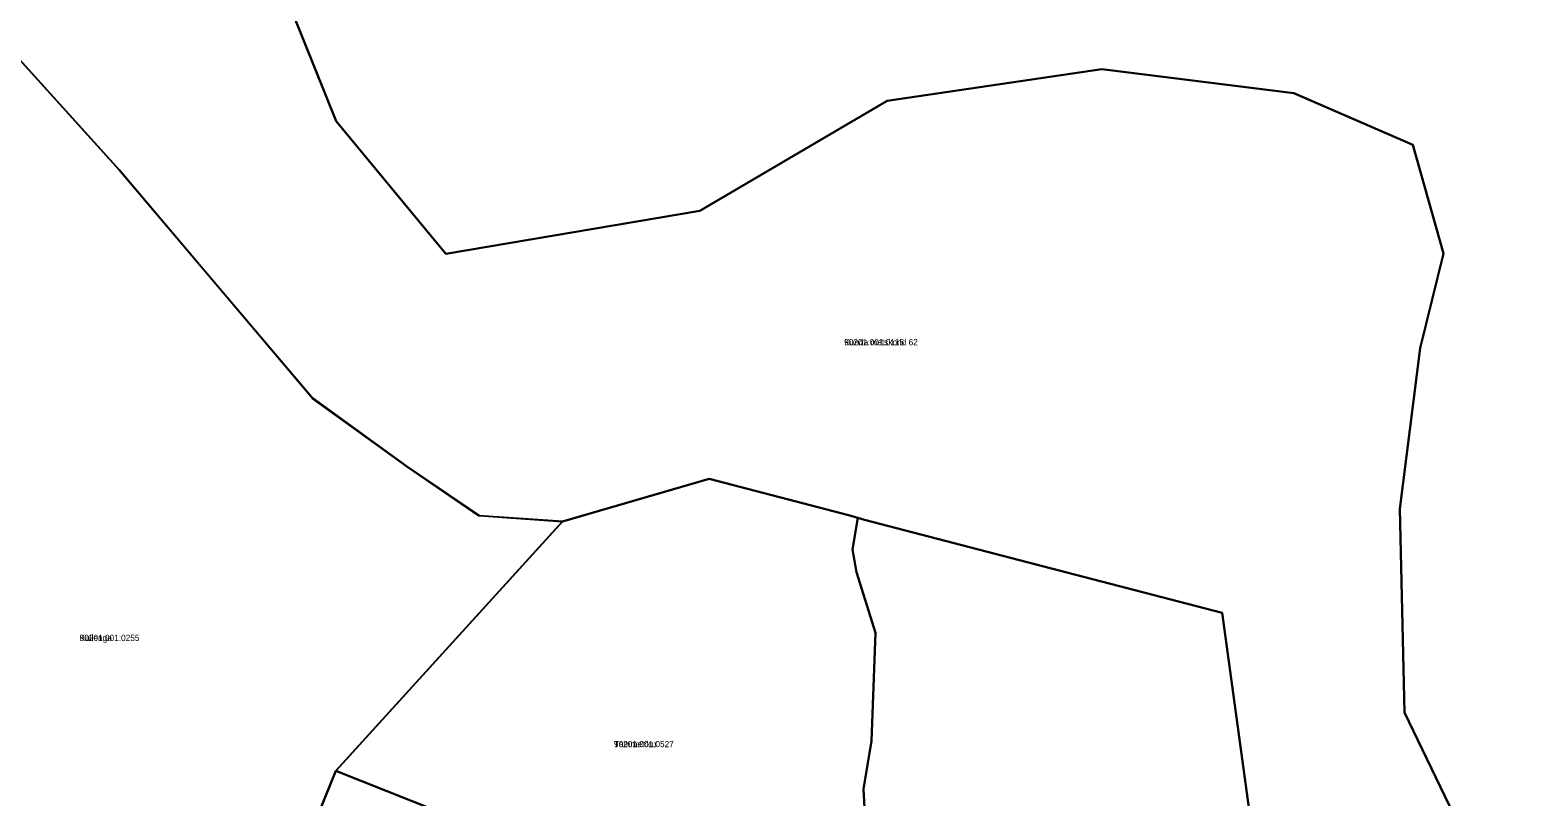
# Model space of a CAD drawing. Extents: x 634518 to 667988, y 6584667 to 6604739.
# Drawn here: x 639044.6 to 639410, y 6599120.4 to 6599306.3 of the extents above; entities that cross this region are included whole.
import ezdxf

# ---------------------------------------------------------------- set-up
doc = ezdxf.new("R2010")
doc.units = 0
for name, color, linetype in [('L_AADRESS', 7, 'Continuous'), ('PIIR', 7, 'Continuous'), ('TUNNUS', 7, 'Continuous')]:
    doc.layers.add(name, color=color, linetype=linetype)

msp = doc.modelspace()

# ---------------------------------------------------------------- linework, layer by layer
at = {"layer": 'PIIR'}
for points in [[(639100.56, 6599329.51), (639118.72, 6599284.25), (639145.3, 6599252.04), (639206.86, 6599262.51), (639252.25, 6599289.18), (639304.28, 6599296.85), (639350.81, 6599291.05), (639379.7, 6599278.52), (639387.08, 6599252.18), (639381.42, 6599229.17), (639376.55, 6599190.19), (639377.67, 6599140.79), (639393.99, 6599106.97), (639433.76, 6599069.98)], [(639433.76, 6599069.98), (639393.99, 6599106.97), (639377.67, 6599140.79), (639376.55, 6599190.19), (639381.42, 6599229.17), (639387.08, 6599252.18), (639379.7, 6599278.52), (639350.81, 6599291.05), (639304.28, 6599296.85), (639252.25, 6599289.18), (639206.86, 6599262.51), (639145.3, 6599252.04), (639118.72, 6599284.25), (639100.56, 6599329.51)], [(639441.3, 6598996.4), (639404.07, 6599015.97), (639378.12, 6599039.05), (639355.62, 6599071.96), (639341.87, 6599103.62), (639333.44, 6599165.02), (639297.96, 6599174.25), (639246.74, 6599187.59), (639245.19, 6599188.04), (639243.23, 6599188.58), (639209.09, 6599197.48), (639173.59, 6599187.14), (639153.27, 6599188.56), (639136.08, 6599200.34), (639113.01, 6599217.01), (639066.11, 6599272.45), (639036.47, 6599305.14), (638997.65, 6599321.26)]]:
    msp.add_lwpolyline(points, dxfattribs=at)
for points in [[(638939.52, 6598922.84), (638956.22, 6599045.86), (638963.81, 6599131.43), (639036.47, 6599305.14), (639066.16, 6599272.46), (639113.06, 6599217.03), (639136.09, 6599200.35), (639153.39, 6599188.58), (639173.59, 6599187.14), (639118.65, 6599126.67), (639114.82, 6599117.34), (639093.64, 6599086.65), (639078.76, 6599065.25), (639063.55, 6599043.7), (639051.11, 6599025.24), (639040.95, 6598997.58), (639033.5, 6598975.34), (639064.36, 6598966.67), (639057.8, 6598941.11), (639047.63, 6598901.35)], [(639143.03, 6599116.99), (639118.65, 6599126.67), (639173.59, 6599187.14), (639209.09, 6599197.48), (639243.23, 6599188.58), (639245.19, 6599188.04), (639243.83, 6599180.32), (639244.87, 6599174.9), (639249.45, 6599160.16), (639248.51, 6599133.96), (639246.5, 6599122.2), (639247.04, 6599113.24), (639245.63, 6599106.61), (639243.91, 6599100), (639242.74, 6599096.83), (639238.97, 6599090.63), (639222.06, 6599067.35), (639220.59, 6599068.27)], [(639295.43, 6599007.23), (639223.67, 6599066.34), (639222.06, 6599067.35), (639238.97, 6599090.63), (639242.74, 6599096.83), (639243.91, 6599100), (639245.63, 6599106.61), (639247.04, 6599113.24), (639246.5, 6599122.2), (639248.51, 6599133.96), (639249.45, 6599160.16), (639244.87, 6599174.9), (639243.83, 6599180.32), (639245.19, 6599188.04), (639246.74, 6599187.59), (639297.96, 6599174.25), (639333.44, 6599165.02), (639341.87, 6599103.62), (639355.62, 6599071.96)], [(639166.41, 6599091.4), (639138.6, 6599108), (639114.82, 6599117.34), (639118.65, 6599126.67), (639143.03, 6599116.99), (639220.59, 6599068.27), (639222.06, 6599067.35), (639223.67, 6599066.34), (639295.43, 6599007.23), (639321.52, 6598983.41), (639346.67, 6598960.5), (639375.78, 6598947.36), (639371.97, 6598938.2), (639341.23, 6598951.98), (639313.88, 6598975.86), (639288.82, 6598999.72), (639259.24, 6599023.6), (639238.53, 6599036.45), (639217.78, 6599059.27), (639187.67, 6599076.21)]]:
    msp.add_lwpolyline(points, close=True, dxfattribs=at)

# ---------------------------------------------------------------- texts
at = {"layer": 'L_AADRESS'}
for s, p in [('Kunda metskond 62', (639241.86, 6599229.88)), ('Kullenga', (639056.56, 6599158.18)), ('Tammetõru', (639186.06, 6599132.42))]:
    msp.add_text(s, height=1.5, dxfattribs=at).set_placement(p)
at = {"layer": 'TUNNUS'}
for s, p in [('90201:001:0115', (639241.86, 6599229.88)), ('90201:001:0255', (639056.56, 6599158.18)), ('90201:001:0527', (639186.06, 6599132.42))]:
    msp.add_text(s, height=1.5, dxfattribs=at).set_placement(p)

doc.saveas('drawing.dxf')
